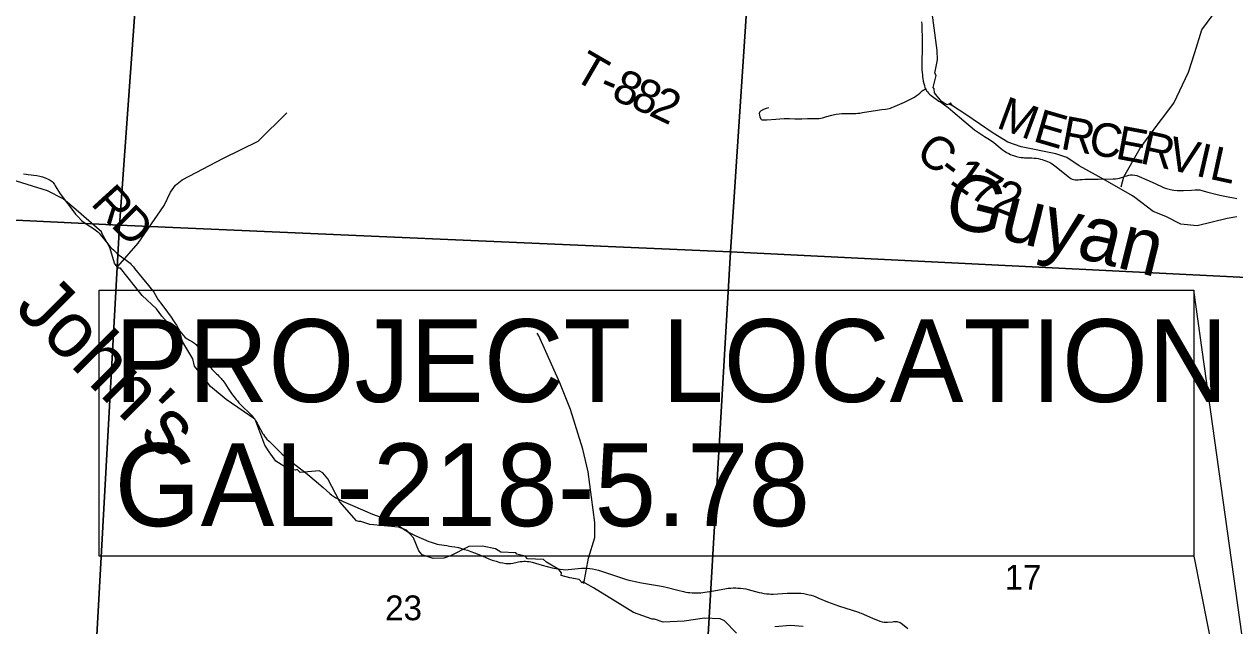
# Model space of a CAD drawing. Extents: x 0 to 34, y 0 to 22.
# Drawn here: x 25.071 to 27.118, y 18.921 to 19.939 of the extents above; entities that cross this region are included whole.
import ezdxf

# ---------------------------------------------------------------- set-up
doc = ezdxf.new("R2010")
doc.units = 0
for name, color, linetype in [('GM_X_County_Road', 7, 'Continuous'), ('GM_X_County_Road_Text', 7, 'Continuous'), ('GM_X_Minor_River', 7, 'Continuous'), ('GM_X_Minor_River_Text', 7, 'Continuous'), ('GM_X_Section', 7, 'Continuous'), ('GM_X_Section_Text', 7, 'Continuous'), ('GM_X_Township_Road', 7, 'Continuous'), ('GM_X_Township_Road_Text', 7, 'Continuous'), ('SH_Masking', 7, 'Continuous'), ('SH_Text', 7, 'Continuous')]:
    doc.layers.add(name, color=color, linetype=linetype)

msp = doc.modelspace()

# ---------------------------------------------------------------- linework, layer by layer
at = {"layer": 'GM_X_County_Road'}
for points in [[(26.5889, 19.9426), (26.5891, 19.9381), (26.5894, 19.932), (26.5895, 19.9264), (26.5896, 19.9206), (26.5896, 19.8998), (26.5893, 19.872), (26.5893, 19.8666), (26.5895, 19.8608), (26.5898, 19.8566), (26.5901, 19.8528), (26.5905, 19.8496), (26.5909, 19.8466), (26.5917, 19.8423), (26.5926, 19.8381), (26.5935, 19.8346), (26.5944, 19.8317), (26.5955, 19.8291), (26.5964, 19.8273), (26.5974, 19.8256), (26.5986, 19.8239), (26.6003, 19.822), (26.6021, 19.8203), (26.6052, 19.8177), (26.6181, 19.8085), (26.623, 19.8053), (26.6274, 19.8023), (26.6336, 19.7977), (26.6419, 19.791), (26.6601, 19.7751), (26.6783, 19.7601), (26.6953, 19.7488), (26.7034, 19.7434), (26.7061, 19.7417), (26.7085, 19.7401), (26.7107, 19.7383), (26.7253, 19.7265), (26.7286, 19.7241), (26.7323, 19.7217), (26.7363, 19.7196), (26.739, 19.7182), (26.7417, 19.7171), (26.7444, 19.7162), (26.7493, 19.7149), (26.7536, 19.7139), (26.7574, 19.7133), (26.7604, 19.7129), (26.7631, 19.7127), (26.775, 19.7124), (26.7789, 19.7122), (26.7824, 19.7118), (26.786, 19.7112), (26.7896, 19.7105), (26.7926, 19.7097), (26.7954, 19.7088), (26.7988, 19.7076), (26.8018, 19.7064), (26.8047, 19.7051), (26.8078, 19.7033), (26.8118, 19.7007), (26.8161, 19.6972), (26.8282, 19.6876), (26.8389, 19.6791), (26.8412, 19.6777), (26.8434, 19.6767), (26.8459, 19.6758), (26.8484, 19.6753), (26.8512, 19.6752), (26.8538, 19.6754), (26.8565, 19.6757), (26.8602, 19.676), (26.8647, 19.6763), (26.8874, 19.6764), (26.9125, 19.6769), (26.9167, 19.6771), (26.9203, 19.6775), (26.9237, 19.6782), (26.9266, 19.679), (26.9309, 19.6805), (26.933, 19.6814), (26.9358, 19.6823), (26.9392, 19.6832), (26.9421, 19.6836), (26.9454, 19.6836), (26.9492, 19.6832), (26.9526, 19.6825), (26.9565, 19.6811), (26.9698, 19.6753), (26.9838, 19.669), (26.9968, 19.663), (27.0007, 19.6615), (27.0051, 19.66), (27.0097, 19.6589), (27.0153, 19.6579), (27.0208, 19.6575), (27.0259, 19.6573), (27.0318, 19.6574), (27.0451, 19.6579), (27.0516, 19.6584), (27.0557, 19.6586), (27.0594, 19.6582), (27.0625, 19.6575), (27.0726, 19.6543), (27.0796, 19.6526), (27.0929, 19.6494), (27.1099, 19.6461), (27.1166, 19.6449), (27.122, 19.6436)], [(25.0704, 19.6853), (25.0745, 19.6847), (25.0784, 19.6842), (25.083, 19.6837), (25.0876, 19.6833), (25.0926, 19.6826), (25.0977, 19.6815), (25.1025, 19.6802), (25.1069, 19.6785), (25.1118, 19.6764), (25.1153, 19.6747), (25.1171, 19.6735), (25.1188, 19.6723), (25.1203, 19.6707), (25.1216, 19.6689), (25.1227, 19.6672), (25.124, 19.6649), (25.1321, 19.6517), (25.1535, 19.6233), (25.1584, 19.6175), (25.1632, 19.612), (25.1686, 19.6068), (25.1745, 19.602), (25.1811, 19.5975), (25.187, 19.594), (25.1892, 19.5926), (25.1916, 19.5909), (25.1938, 19.5891), (25.196, 19.5871), (25.1981, 19.585), (25.1999, 19.583), (25.2128, 19.5668), (25.2146, 19.5646), (25.2167, 19.5622), (25.219, 19.5598), (25.2229, 19.5561), (25.2282, 19.5512), (25.2322, 19.5479), (25.2439, 19.5394), (25.2462, 19.5379), (25.2485, 19.5362), (25.2505, 19.5342), (25.2523, 19.5323), (25.2544, 19.5298), (25.256, 19.5279), (25.258, 19.5254), (25.2708, 19.5097), (25.2818, 19.4964), (25.2882, 19.4884), (25.2893, 19.4869), (25.2905, 19.4852), (25.2981, 19.4725), (25.3039, 19.4643), (25.3138, 19.4515), (25.3199, 19.4429), (25.3241, 19.4368), (25.3264, 19.4334), (25.3289, 19.4294), (25.3348, 19.4194), (25.3372, 19.4158), (25.34, 19.4125), (25.343, 19.4095), (25.3469, 19.4066), (25.3494, 19.405)], [(25.3494, 19.405), (25.3511, 19.4039), (25.3559, 19.4012), (25.3594, 19.3988), (25.3608, 19.3978), (25.3621, 19.3967), (25.3636, 19.3953), (25.3647, 19.3939), (25.3657, 19.3924), (25.3665, 19.3908), (25.3672, 19.3893), (25.3678, 19.3878), (25.3724, 19.3773), (25.3741, 19.3744), (25.376, 19.3712), (25.3837, 19.361), (25.3863, 19.3578), (25.3895, 19.3543), (25.3965, 19.3473), (25.3986, 19.3453), (25.4004, 19.3435), (25.4024, 19.3415), (25.4043, 19.3395), (25.4058, 19.3377), (25.4074, 19.3358), (25.409, 19.3337), (25.4106, 19.3315), (25.4162, 19.3226), (25.4219, 19.314), (25.4298, 19.3038), (25.4319, 19.3013), (25.4346, 19.2983), (25.4413, 19.2912), (25.4516, 19.2815), (25.4538, 19.2794), (25.4556, 19.2773), (25.4576, 19.275), (25.4593, 19.273), (25.4607, 19.271), (25.462, 19.2691), (25.4632, 19.2674), (25.4643, 19.2655), (25.4654, 19.2635), (25.4665, 19.2615), (25.4709, 19.2528), (25.473, 19.2491), (25.4746, 19.2464), (25.4758, 19.2445), (25.4777, 19.2419), (25.4797, 19.2394), (25.4819, 19.2367), (25.4855, 19.2331), (25.4937, 19.2253), (25.5079, 19.2114), (25.5261, 19.196), (25.5386, 19.1867), (25.543, 19.1833), (25.5477, 19.1796), (25.5544, 19.1741), (25.5615, 19.1681), (25.5771, 19.155), (25.5882, 19.1449), (25.5919, 19.1418), (25.5951, 19.1396), (25.5985, 19.1375), (25.6027, 19.1351), (25.611, 19.1314), (25.6264, 19.1244), (25.6433, 19.117), (25.6606, 19.11), (25.6742, 19.1048), (25.6814, 19.1023), (25.6875, 19.0999), (25.6913, 19.0982), (25.6948, 19.0965), (25.6985, 19.0945), (25.7019, 19.0925), (25.705, 19.0904), (25.708, 19.0882), (25.7125, 19.0848), (25.7166, 19.0821), (25.7204, 19.08), (25.7248, 19.0776), (25.7337, 19.0734), (25.7556, 19.0639), (25.7595, 19.0623), (25.7632, 19.0611), (25.7664, 19.06), (25.7696, 19.0593), (25.7732, 19.0585), (25.7863, 19.0566), (25.7907, 19.056), (25.7945, 19.0554), (25.7998, 19.0545), (25.8056, 19.0532), (25.8157, 19.0503), (25.8212, 19.0487), (25.8268, 19.0469), (25.8328, 19.0446), (25.84, 19.0416), (25.8509, 19.0369), (25.8572, 19.0343), (25.8629, 19.0322), (25.8694, 19.0301), (25.8757, 19.0283), (25.8807, 19.0273), (25.8857, 19.0267), (25.8903, 19.0264), (25.8944, 19.0266), (25.8979, 19.0271), (25.9051, 19.0287), (25.9075, 19.0292), (25.9103, 19.0297), (25.9132, 19.0299), (25.916, 19.0301), (25.9189, 19.0301), (25.9221, 19.0299), (25.9253, 19.0296), (25.9281, 19.029), (25.9303, 19.0284), (25.9474, 19.0235), (25.964, 19.0191), (25.9731, 19.0173), (25.9779, 19.0166), (25.9826, 19.0161), (25.9874, 19.0158), (25.9915, 19.016), (26.0137, 19.0183), (26.0182, 19.0185), (26.0231, 19.0183), (26.0279, 19.018), (26.0326, 19.0174), (26.0374, 19.0164), (26.0424, 19.015), (26.0478, 19.0133), (26.0833, 19.0015), (26.0881, 19), (26.0938, 18.9984), (26.0992, 18.997), (26.1047, 18.9958), (26.1153, 18.9937), (26.1457, 18.9884), (26.1521, 18.9873), (26.1568, 18.9862), (26.1766, 18.9811), (26.1864, 18.9789), (26.1903, 18.9782), (26.1938, 18.9776), (26.1972, 18.9772), (26.2011, 18.9768), (26.2061, 18.9766), (26.2118, 18.9768), (26.2154, 18.977), (26.2188, 18.9773), (26.2223, 18.9778), (26.226, 18.9784), (26.2301, 18.9791), (26.234, 18.9798), (26.256, 18.9836), (26.2616, 18.9845), (26.2661, 18.9848), (26.2705, 18.985), (26.2748, 18.985), (26.2783, 18.9848), (26.2828, 18.9845), (26.2872, 18.984), (26.2915, 18.9833), (26.2955, 18.9824), (26.3141, 18.9776), (26.3181, 18.9767), (26.322, 18.9759), (26.3267, 18.9752), (26.331, 18.9749), (26.3341, 18.9747), (26.3378, 18.9748), (26.3617, 18.9761), (26.3706, 18.9764), (26.3753, 18.9765), (26.3801, 18.9764), (26.3848, 18.9761), (26.3896, 18.9756), (26.394, 18.9748), (26.3986, 18.9737), (26.4021, 18.9728), (26.4059, 18.9717), (26.4098, 18.9701), (26.4134, 18.9686), (26.4296, 18.9618), (26.4486, 18.9548), (26.4822, 18.944), (26.4843, 18.9432), (26.4869, 18.9423), (26.5056, 18.9337), (26.5099, 18.932), (26.514, 18.9303), (26.5184, 18.9289), (26.5219, 18.928), (26.5253, 18.9274), (26.5285, 18.9272), (26.5314, 18.9273), (26.5394, 18.928), (26.5421, 18.9282), (26.5443, 18.9283), (26.5468, 18.9281), (26.5489, 18.9278), (26.5511, 18.9272), (26.5526, 18.9265), (26.5542, 18.9256), (26.5568, 18.9237), (26.5658, 18.9167)]]:
    msp.add_lwpolyline(points, dxfattribs=at)
at = {"layer": 'GM_X_Minor_River'}
for points in [[(26.9263, 19.6632), (26.9309, 19.6802), (26.9584, 19.7286), (26.9754, 19.752), (27.0152, 19.8051), (27.0402, 19.8574), (27.051, 19.8905), (27.0628, 19.9288), (27.0896, 19.9656), (27.1198, 20.0265), (27.1878, 20.1143), (27.2041, 20.1286)], [(27.1219, 19.6125), (27.1056, 19.6098), (27.0546, 19.5975), (27.027, 19.6001), (27.0017, 19.6133), (26.9805, 19.622), (26.9495, 19.6455), (26.9453, 19.6482), (26.8992, 19.675), (26.8553, 19.6989), (26.8345, 19.7129), (26.816, 19.7193), (26.757, 19.731), (26.7347, 19.7389), (26.7097, 19.7544), (26.6636, 19.7858), (26.6412, 19.8002), (26.6378, 19.8055), (26.6356, 19.8032), (26.6382, 19.8021), (26.636, 19.8025), (26.6375, 19.8044), (26.6314, 19.8021), (26.6227, 19.8078), (26.6106, 19.8226), (26.6102, 19.829), (26.6083, 19.8317), (26.6136, 19.8518), (26.6113, 19.8556), (26.6158, 19.8785), (26.6151, 19.894), (26.6037, 19.9799)], [(25.2299, 19.529), (25.2641, 19.5681), (25.3081, 19.6321), (25.3186, 19.6546), (25.3272, 19.6664), (25.3386, 19.6752), (25.4082, 19.712), (25.4668, 19.7408), (25.5155, 19.7889)], [(25.2712, 19.4798), (25.2341, 19.5257), (25.2304, 19.5257), (25.2243, 19.5344), (25.2163, 19.561), (25.2035, 19.5838), (25.202, 19.5872), (25.1596, 19.6247), (25.1376, 19.6433), (25.1108, 19.6565), (25.042, 19.678)], [(26.2758, 18.9085), (26.2557, 18.9297), (26.2485, 18.9327), (26.2217, 18.9338), (26.1873, 18.9288), (26.1521, 18.9272), (26.137, 18.9321), (26.1332, 18.9321), (26.1015, 18.9434), (26.0826, 18.9555), (26.0338, 18.9854), (26.016, 18.9956), (26.0149, 18.9937), (26.0096, 18.9994), (25.9941, 19.002), (25.9793, 19.0062), (25.9797, 19.0107), (25.9755, 19.0164), (25.9544, 19.0289), (25.9498, 19.0334), (25.9222, 19.0345), (25.9184, 19.0391), (25.9044, 19.0421), (25.9025, 19.0443), (25.8772, 19.0458), (25.8685, 19.0515), (25.8462, 19.0556), (25.8232, 19.0552), (25.7922, 19.0395), (25.7808, 19.0357), (25.7627, 19.0349), (25.7445, 19.0409), (25.7385, 19.0481), (25.7298, 19.0701), (25.718, 19.083), (25.7041, 19.0879), (25.6557, 19.0923), (25.6405, 19.0976), (25.6375, 19.0976), (25.6334, 19.0988), (25.6054, 19.1306), (25.5849, 19.1697), (25.5766, 19.1799), (25.5701, 19.183), (25.538, 19.1806), (25.5331, 19.1855), (25.5301, 19.1844), (25.5168, 19.187), (25.4972, 19.1995), (25.4858, 19.2154), (25.4782, 19.2264), (25.4631, 19.2671), (25.4612, 19.2705), (25.4128, 19.3038), (25.3867, 19.3258), (25.3696, 19.3478), (25.3594, 19.3603), (25.3568, 19.3728), (25.3394, 19.4005), (25.3367, 19.4081), (25.3042, 19.4445), (25.2951, 19.457), (25.2712, 19.4798)], [(26.0176, 18.9927), (26.0257, 19.0357), (26.0362, 19.0703), (26.0362, 19.0958), (26.0252, 19.1816), (26.0158, 19.2198), (25.9951, 19.2869), (25.9772, 19.3319), (25.9418, 19.4113), (25.9389, 19.4159)], [(26.3884, 18.9198), (26.3672, 18.9213), (26.3404, 18.9193)]]:
    msp.add_lwpolyline(points, dxfattribs=at)
at = {"layer": 'GM_X_Section'}
for points in [[(24.2561, 20.6827), (25.3065, 20.6239), (25.2325, 19.5985), (24.2052, 19.6482)], [(25.3065, 20.6239), (26.3334, 20.5711), (26.2655, 19.5533), (25.2325, 19.5985)], [(26.3334, 20.5711), (27.3906, 20.5203), (27.3196, 19.501), (26.2655, 19.5533)], [(24.2052, 19.6482), (25.2325, 19.5985), (25.1763, 18.5784), (24.1456, 18.6175)], [(25.2325, 19.5985), (26.2655, 19.5533), (26.2062, 18.5294), (25.1763, 18.5784)], [(26.2655, 19.5533), (27.3196, 19.501), (27.254, 18.479), (26.2062, 18.5294)]]:
    msp.add_lwpolyline(points, close=True, dxfattribs=at)
at = {"layer": 'GM_X_Township_Road'}
msp.add_lwpolyline([(26.3301, 19.7971), (26.3262, 19.796), (26.3213, 19.7942), (26.3165, 19.7917), (26.3152, 19.7906), (26.3147, 19.789), (26.3144, 19.7875), (26.3146, 19.7849), (26.3152, 19.782), (26.3158, 19.7803), (26.3168, 19.7785), (26.3178, 19.7774), (26.3191, 19.777), (26.3219, 19.7768), (26.327, 19.777), (26.3426, 19.7782), (26.3492, 19.7785), (26.3566, 19.7789), (26.3612, 19.779), (26.3654, 19.7789), (26.3745, 19.7786), (26.381, 19.7786), (26.3866, 19.7786), (26.3957, 19.7788), (26.4078, 19.779), (26.4133, 19.7792), (26.4156, 19.7792), (26.4183, 19.7796), (26.4212, 19.7803), (26.4264, 19.782), (26.4372, 19.7849), (26.4393, 19.7854), (26.4415, 19.7858), (26.4445, 19.7862), (26.4494, 19.7869), (26.4538, 19.7873), (26.4584, 19.7876), (26.4626, 19.7877), (26.4689, 19.7874), (26.4734, 19.7873), (26.4775, 19.7875), (26.4808, 19.7878), (26.4843, 19.7882), (26.4889, 19.789), (26.514, 19.7934), (26.5177, 19.7939), (26.5214, 19.7943), (26.5276, 19.795), (26.5309, 19.7955), (26.5339, 19.7961), (26.5362, 19.7968), (26.5384, 19.7975), (26.5442, 19.7999), (26.5602, 19.8068), (26.568, 19.8105), (26.5736, 19.8133), (26.5771, 19.8154), (26.5799, 19.8174), (26.5831, 19.8198), (26.5857, 19.8219), (26.5881, 19.824), (26.5899, 19.8256), (26.5917, 19.8268), (26.5936, 19.828), (26.5955, 19.8291)], dxfattribs=at)
at = {"layer": 'SH_Masking'}
msp.add_lwpolyline([(25.198, 19.4888), (27.0492, 19.4888), (27.0492, 19.0391), (25.198, 19.0391)], close=True, dxfattribs=at)
at = {"layer": 'SH_Text'}
for points in [[(25.198, 19.4888), (27.0492, 19.4888), (27.0492, 19.0391), (25.198, 19.0391)], [(27.0492, 19.0391), (27.2621, 17.9634), (27.0492, 19.4888)]]:
    msp.add_lwpolyline(points, close=True, dxfattribs=at)

# ---------------------------------------------------------------- texts
at = {"layer": 'GM_X_County_Road_Text'}
for s, rotation, p in [('M', 339.67, (26.7134, 19.7642)), ('E', 343.7296, (26.7754, 19.7413)), ('R', 349.4099, (26.8221, 19.728)), ('C', 350.5171, (26.8692, 19.7192)), ('E', 349.3137, (26.9149, 19.7116)), ('R', 347.667, (26.9562, 19.7038)), ('C', 321.9763, (26.5762, 19.7156)), ('V', 347.0302, (27.0017, 19.6939)), ('I', 347.0574, (27.0504, 19.6826)), ('L', 347.6943, (27.0738, 19.6773)), ('-', 322.995, (26.6138, 19.6862)), ('1', 324.6859, (26.6339, 19.6711)), ('7', 329.3821, (26.6667, 19.6481)), ('2', 338.7231, (26.7059, 19.6258)), ('R', 312.3317, (25.1824, 19.6345)), ('D', 315.5227, (25.2162, 19.5975))]:
    msp.add_text(s, height=0.0568, rotation=rotation, dxfattribs=at).set_placement(p)
at = {"layer": 'GM_X_Minor_River_Text'}
for s, rotation, p in [('Guyan', 346.0032, (26.6226, 19.6009)), ("John's", 315.0035, (25.0531, 19.456))]:
    msp.add_text(s, height=0.09469, rotation=rotation, dxfattribs=at).set_placement(p)
at = {"layer": 'GM_X_Section_Text'}
for s, p in [('17', (26.7293, 18.9823)), ('23', (25.6818, 18.9305))]:
    msp.add_text(s, height=0.04186, rotation=0, dxfattribs=at).set_placement(p)
at = {"layer": 'GM_X_Township_Road_Text'}
for s, rotation, p in [('T', 329.8543, (25.9969, 19.8469)), ('8', 336.7416, (26.062, 19.813)), ('-', 337.0685, (26.0406, 19.822)), ('8', 336.3405, (26.0941, 19.7992)), ('2', 334.5195, (26.1257, 19.7853))]:
    msp.add_text(s, height=0.0568, rotation=rotation, dxfattribs=at).set_placement(p)
at = {"layer": 'SH_Text'}
for s, p in [('PROJECT LOCATION', (25.2242, 19.2996)), ('GAL-218-5.78', (25.2242, 19.0896))]:
    msp.add_text(s, height=0.14, dxfattribs=at).set_placement(p)

doc.saveas('drawing.dxf')
